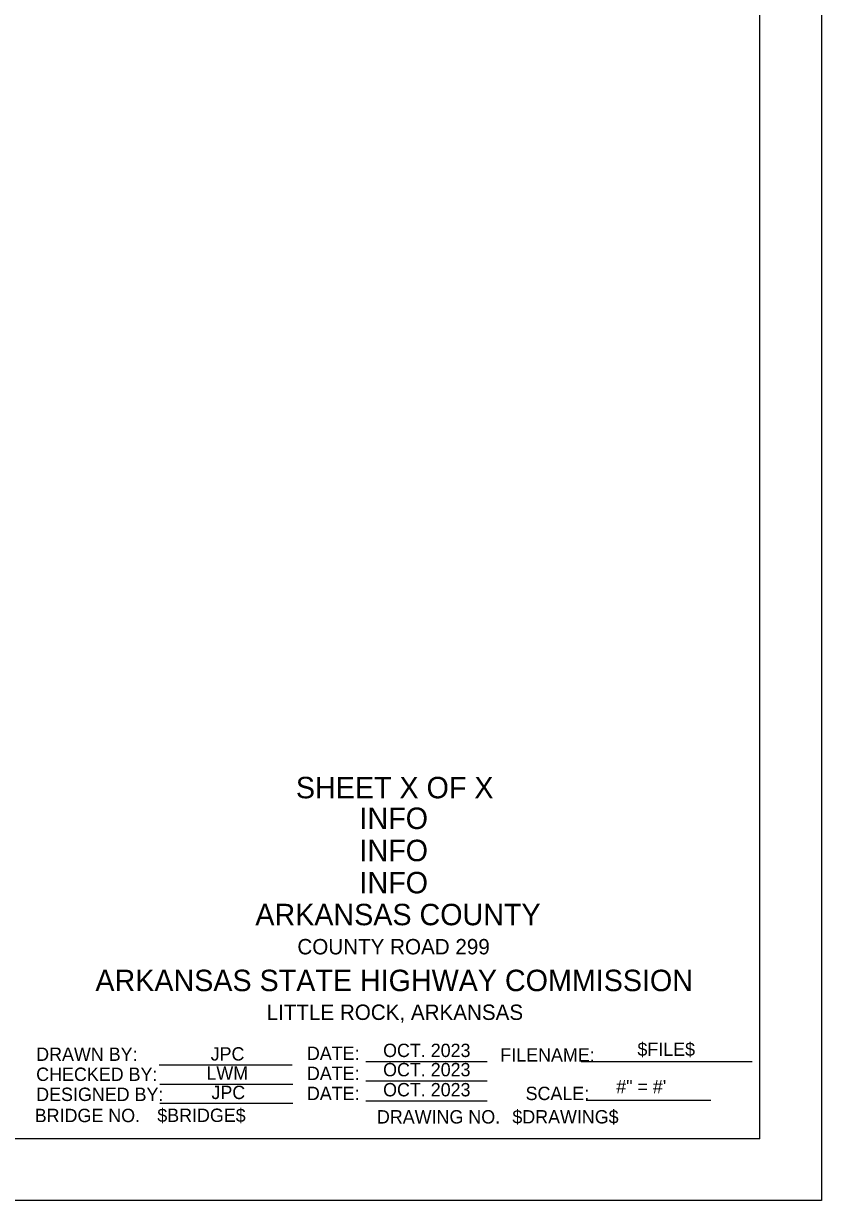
# Model space of a CAD drawing. Extents: x 16 to 1228743, y 11 to 152440.
# Drawn here: x 17.869 to 18.49, y 10.71 to 11.626 of the extents above; entities that cross this region are included whole.
import ezdxf

# ---------------------------------------------------------------- set-up
doc = ezdxf.new("R2010")
doc.units = 0
for name, color, linetype in [('B_Copy In', 7, 'Continuous'), ('B_County and Route', 7, 'Continuous'), ('B_Text', 7, 'Continuous'), ('B_Title Text', 7, 'Continuous'), ('R_Border', 7, 'Continuous')]:
    doc.layers.add(name, color=color, linetype=linetype)

msp = doc.modelspace()

# ---------------------------------------------------------------- linework, layer by layer
at = {"layer": 'B_Text'}
for p, q in [((18.13563, 10.81768), (18.23013, 10.81768)), ((18.30322, 10.81768), (18.43627, 10.81768)), ((17.97453, 10.81518), (18.07813, 10.81518)), ((17.97513, 10.80018), (18.07873, 10.80018)), ((18.13563, 10.80268), (18.23013, 10.80268)), ((18.13563, 10.80268), (18.23013, 10.80268)), ((17.97513, 10.78518), (18.07873, 10.78518)), ((18.13563, 10.78705), (18.23013, 10.78705)), ((18.3071, 10.78768), (18.40423, 10.78768))]:
    msp.add_line(p, q, dxfattribs=at)
at = {"layer": 'R_Border'}
for q in [(18.44224, 12.49478), (15.7833, 10.75758)]:
    msp.add_line((18.44224, 10.75758), q, dxfattribs=at)
msp.add_lwpolyline([(15.65697, 12.54285), (18.49031, 12.54285), (18.49031, 10.70951), (15.65697, 10.70951)], close=True, dxfattribs=at)

# ---------------------------------------------------------------- texts
at = {"layer": 'B_Copy In'}
for s, height, p in [('SHEET X OF X', 0.0167, (18.08106, 11.02274)), ('INFO', 0.0167, (18.1306, 10.99881)), ('INFO', 0.0167, (18.1306, 10.97376)), ('INFO', 0.0167, (18.1306, 10.94871)), ('JPC', 0.0104, (18.01471, 10.81848)), ('OCT. 2023', 0.0104, (18.14899, 10.82121)), ('OCT. 2023', 0.0104, (18.14899, 10.80621)), ('LWM', 0.0104, (18.01142, 10.80348)), ('JPC', 0.0104, (18.01531, 10.78848)), ('OCT. 2023', 0.0104, (18.14899, 10.79059)), ('#" = #\'', 0.0104, (18.33054, 10.79304))]:
    msp.add_text(s, height=height, dxfattribs=at).set_placement(p)
at = {"layer": 'B_County and Route'}
msp.add_text('ARKANSAS COUNTY', height=0.0167, dxfattribs=at).set_placement((18.0495, 10.92386))
at = {"layer": 'B_Text'}
for s, height, p in [('DRAWN BY:', 0.010417, (17.87883, 10.81822)), ('DATE:', 0.010417, (18.08963, 10.81893)), ('FILENAME:', 0.010417, (18.24021, 10.81768)), ('CHECKED BY:', 0.0104167, (17.87883, 10.80259)), ('DATE:', 0.010417, (18.08963, 10.8033)), ('DESIGNED BY:', 0.0104167, (17.87883, 10.78697)), ('DATE:', 0.010417, (18.08963, 10.78768)), ('SCALE:', 0.010417, (18.25993, 10.78768)), ('BRIDGE NO.', 0.010417, (17.8777, 10.7705)), ('DRAWING NO.', 0.0104166, (18.14416, 10.76944))]:
    msp.add_text(s, height=height, dxfattribs=at).set_placement(p)
at = {"layer": 'B_Title Text'}
for s, height, p in [('COUNTY ROAD 299', 0.012, (18.08223, 10.90117)), ('ARKANSAS STATE HIGHWAY COMMISSION', 0.0167, (17.92495, 10.87253)), ('LITTLE ROCK, ARKANSAS', 0.012, (18.05826, 10.8501))]:
    msp.add_text(s, height=height, dxfattribs=at).set_placement(p)
at = {"layer": 'R_Border'}
for s, p in [('$FILE$', (18.347, 10.82212)), ('$BRIDGE$', (17.97316, 10.77064)), ('$DRAWING$', (18.24965, 10.76948))]:
    msp.add_text(s, height=0.0104, dxfattribs=at).set_placement(p)

doc.saveas('drawing.dxf')
